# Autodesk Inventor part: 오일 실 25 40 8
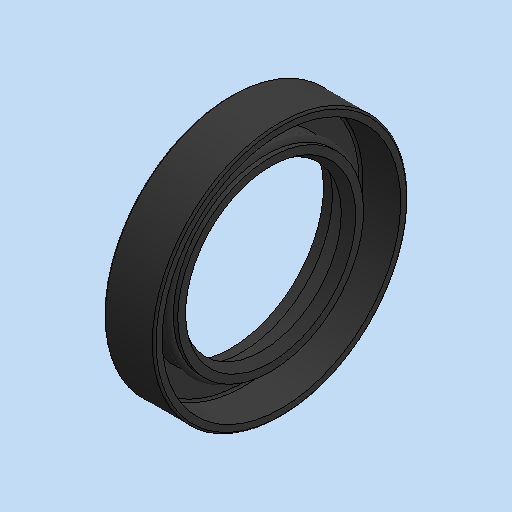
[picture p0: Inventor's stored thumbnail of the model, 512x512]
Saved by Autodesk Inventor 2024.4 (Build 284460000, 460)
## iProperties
Created: 2025-11
Part Number: 오일 실 25 40 8
Material: 고무
Description: 오일-실
Document SubType Name: Modeling
Designer: home
Density: 0.93 g/cm^3
Appearance: 기본값
Author: jhkim
Sending System: Autodesk Inventor 2026
Preprocessor: ST-DEVELOPER v20.1
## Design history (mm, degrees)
feature "Solid1"
node "솔리드1"
